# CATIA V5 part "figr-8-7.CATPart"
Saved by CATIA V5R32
Part number: Part1
Bounding box of the stored display mesh (mm): x 4.549 to 89.781, y -52.238 to 26.36, z 54 to 147.773
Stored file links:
  D:\PROJECTS\Project 2022\CATIA V5 6R 2022\Resources\Part Files\c08_catia_v5_6r2022_prt\figr-8-7.CATPart
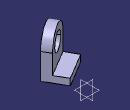
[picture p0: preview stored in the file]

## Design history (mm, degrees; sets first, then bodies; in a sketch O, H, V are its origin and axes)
Body1 (main body)
  Sketch1 on yz-plane, origin (0, 0, 0), H (0, 1, 0), V (0, 0, 1)
    point P1 (-104.4861, 0)
    line L1 (-104.4861, 0) -> (-104.4861, 44.267)
    arc A1 centre (-69.7903, 44.267) radius 34.6958 from (-104.4861, 44.267) to (-35.0946, 44.267) cw
    line L2 (-35.0946, 44.267) -> (-35.0946, 0)
    point P5 (-35.0946, 0)
    line L3 (-35.0946, 0) -> (-104.4861, 0)
    circle A2 centre (-69.7903, 44.267) radius 19.5413
    coincidence: P1 H, P5 H
    vertical: L1 V
    tangency: A1 L1, L2 A1
    horizontal: L3 H
  Pad1: profile Sketch1, direction (1, 0, 0), length 20
  Sketch2 on face of Pad1, origin (0, 0, 0), H (0, -1, 0), V (0, 0, 1)
    point P1 (35.0946, 0)
    line L1 (35.0946, 0) -> (104.4861, 0)
    line L2 (104.4861, 0) -> (104.4861, -15)
    line L3 (104.4861, -15) -> (35.0946, -15)
    line L4 (35.0946, -15) -> (35.0946, 0)
    reference projected line E1 (35.0946, 0) -> (35.0946, 44.267) from edge [face of Pad1 | face of Pad1]
    reference projected line E2 (104.4861, 44.267) -> (104.4861, 0) from edge [face of Pad1 | face of Pad1]
    distance L3 L1 = 15
    coincidence: P1 H, L4 E1, L2 E2
    horizontal: L1 H, L3 H
    vertical: L2 V, L4 V
  Pad2: profile Sketch2, direction (1, 0, 0), length 50
  Translate1: Direction xy-plane, ToTransfor Pad2, Length 69
  Rotate1: Axis edge, ToTransfor Translate1, Angle 121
